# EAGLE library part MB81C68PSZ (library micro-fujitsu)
MICROCONTROLLER/MEMORY DEVICE
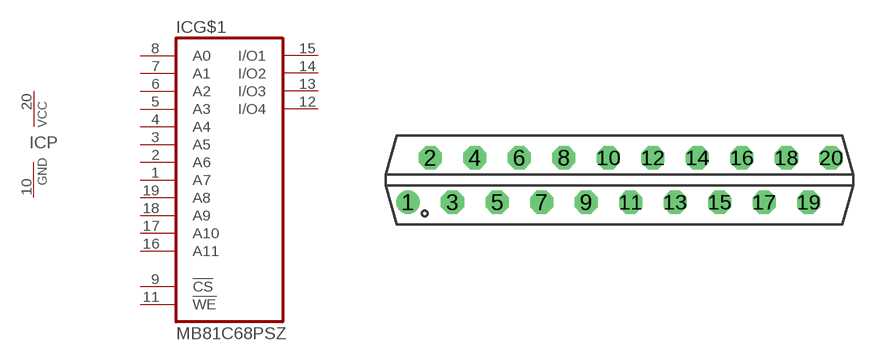
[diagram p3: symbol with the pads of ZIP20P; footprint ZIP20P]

Designator prefix IC; gates G$1=MB81C68 P=VCC-GND

## MB81C68PSZ (OC_FARNELL: unknown; OC_NEWARK: unknown)  [ZIP20P]
1  G$1:A7  in
2  G$1:A6  in
3  G$1:A5  in
4  G$1:A4  in
5  G$1:A3  in
6  G$1:A2  in
7  G$1:A1  in
8  G$1:A0  in
9  G$1:!CS  in
10  P:GND  pwr
11  G$1:!WE  in
12  G$1:I/O4
13  G$1:I/O3
14  G$1:I/O2
15  G$1:I/O1
16  G$1:A11  in
17  G$1:A10  in
18  G$1:A9  in
19  G$1:A8  in
20  P:VCC  pwr

## Footprint ZIP20P (pad centres in mm)
Single In Line
drill 0.813 round: 1 -10.16,-1.27
drill 0.813 octagon: 2 -8.89,1.27; 3 -7.62,-1.27; 4 -6.35,1.27; 5 -5.08,-1.27; 6 -3.81,1.27; 7 -2.54,-1.27; 8 -1.27,1.27; 9 0,-1.27; 10 1.27,1.27; 11 2.54,-1.27; 12 3.81,1.27; 13 5.08,-1.27; 14 6.35,1.27; 15 7.62,-1.27; 16 8.89,1.27; 17 10.16,-1.27; 18 11.43,1.27; 19 12.7,-1.27; 20 13.97,1.27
